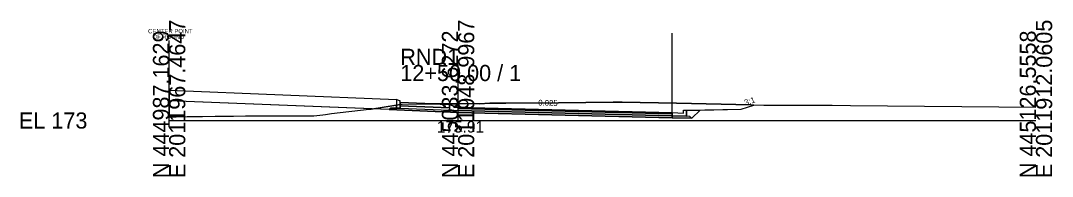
# Model space of a CAD drawing. Extents: x -26 to 153, y -10 to 6017.
# Drawn here: x -25.7 to 152.8, y 4990.3 to 5017.3 of the extents above; entities that cross this region are included whole.
import ezdxf

# ---------------------------------------------------------------- set-up
doc = ezdxf.new("R2010")
doc.units = 0
for name, color, linetype in [('Exist Cross Section Cell', 7, 'Continuous'), ('Exist XS Ground Line', 7, 'Continuous'), ('Prop CMT Conc Surface', 7, 'Continuous'), ('Prop CMT Concrete Structures', 7, 'Continuous'), ('Prop CMT Pvmt Course 1', 7, 'Continuous'), ('Prop CMT Pvmt Course 1 CG', 7, 'Continuous'), ('Prop CMT Pvmt Course 2', 7, 'Continuous'), ('Prop CMT Pvmt Course 3', 7, 'Continuous'), ('Prop CMT Pvmt Surface', 7, 'Continuous'), ('Prop CMT Shear Line', 7, 'Continuous'), ('Prop CMT Shear Line Text', 7, 'Continuous'), ('Prop CMT Slope Grass', 7, 'Continuous'), ('Prop CMT Subgrade Earthwork', 7, 'Continuous'), ('Prop XS Earthwork Shape', 7, 'Continuous'), ('Prop XS SE Text', 7, 'Continuous'), ('Prop XS Side Slope Text', 7, 'Continuous'), ('Scratch_Level_1', 7, 'Continuous')]:
    doc.layers.add(name, color=color, linetype=linetype)

msp = doc.modelspace()

# ---------------------------------------------------------------- linework, layer by layer
at = {"layer": 'Exist Cross Section Cell'}
for p, q in [((50, 5000), (50, 5009.64)), ((0, 5000), (50, 5000)), ((50, 5000), (150, 5000))]:
    msp.add_line(p, q, dxfattribs=at)
at = {"layer": 'Exist XS Ground Line'}
msp.add_lwpolyline([(0, 5000.62), (0.45, 5000.62), (1.21, 5000.65), (3.1, 5000.71), (4.34, 5000.71), (5.78, 5000.7), (7.98, 5000.75), (8.46, 5000.76), (8.92, 5000.77), (9.3, 5000.77), (11.15, 5000.77), (13.23, 5000.79), (14.09, 5000.8), (14.73, 5000.8), (16.55, 5000.82), (17.74, 5000.82), (19.21, 5000.82), (20.44, 5000.83), (21.66, 5000.84), (23.37, 5000.84), (24.41, 5000.84), (25.04, 5000.82), (25.54, 5000.87), (26.58, 5001), (27.09, 5001.06), (28.12, 5001.2), (34.63, 5001.94), (34.98, 5001.99), (40.35, 5002.86), (50, 5002.91), (52.83, 5002.93), (53.71, 5002.92), (55.52, 5002.98), (58.29, 5002.98), (67.4, 5003.08), (76.85, 5003.21), (77.24, 5003.21), (78.41, 5003.2), (87.81, 5003.01), (100.67, 5002.69), (102.93, 5002.64), (105.36, 5002.65), (108.91, 5002.66), (110.4, 5002.67), (111.72, 5002.68), (112.15, 5002.68), (114.72, 5002.66), (117.91, 5002.61), (150, 5002.32)], dxfattribs=at)
at = {"layer": 'Prop CMT Conc Surface'}
for points in [[(40, 5003.29), (39.96, 5003.39), (39.85, 5003.43), (39.34, 5003.62)], [(40, 5003.12), (40, 5003.29)], [(50, 5002.32), (49.25, 5002.34), (49.25, 5002.51), (48.5, 5002.76)], [(87.04, 5001.4), (89.03, 5001.27)], [(89.03, 5001.27), (89.03, 5001.77), (89.53, 5001.77)]]:
    msp.add_lwpolyline(points, dxfattribs=at)
at = {"layer": 'Prop CMT Concrete Structures'}
for points in [[(40, 5003.29), (39.96, 5003.39), (39.85, 5003.43), (39.34, 5003.62)], [(39.34, 5003.62), (39.34, 5002.12)], [(40, 5003.12), (40, 5003.29)], [(40, 5002.12), (40, 5003.12)], [(40, 5003.12), (40, 5002.54)], [(48.5, 5002.76), (40, 5003.1)], [(40, 5002.52), (48.5, 5002.18)], [(50, 5002.32), (49.25, 5002.34), (49.25, 5002.51), (48.5, 5002.76)], [(48.5, 5002.76), (48.5, 5001.78)], [(48.5, 5002.18), (48.5, 5002.76)], [(39.34, 5002.12), (40, 5002.12)], [(48.5, 5001.78), (50, 5001.74)], [(50, 5001.74), (50, 5002.32)], [(87.04, 5001.4), (89.03, 5001.27), (89.03, 5001.77), (89.53, 5001.77)], [(89.53, 5001.77), (89.53, 5000.75), (87.04, 5000.81)], [(87.04, 5000.81), (87.04, 5001.4)]]:
    msp.add_lwpolyline(points, dxfattribs=at)
at = {"layer": 'Prop CMT Pvmt Course 1'}
for points in [[(50, 5002.32), (87.04, 5001.4)], [(50, 5002.07), (50, 5002.32)], [(87.04, 5001.15), (50, 5002.07)], [(87.04, 5001.4), (87.04, 5001.15)]]:
    msp.add_lwpolyline(points, dxfattribs=at)
msp.add_lwpolyline([(50, 5002.07), (50, 5002.2), (50, 5002.2), (50, 5002.07)], close=True, dxfattribs=at)
at = {"layer": 'Prop CMT Pvmt Course 1 CG'}
for points in [[(50, 5001.41), (50, 5001.74)], [(87.04, 5000.81), (90.03, 5000.74), (90.37, 5000.4)], [(87.04, 5000.48), (87.04, 5000.81)], [(90.45, 5000.39), (87.04, 5000.48)]]:
    msp.add_lwpolyline(points, dxfattribs=at)
at = {"layer": 'Prop CMT Pvmt Course 2'}
for points in [[(50, 5001.74), (50, 5002.07)], [(50, 5002.07), (87.04, 5001.15)], [(87.04, 5000.81), (50, 5001.74)], [(87.04, 5001.15), (87.04, 5000.81)]]:
    msp.add_lwpolyline(points, dxfattribs=at)
at = {"layer": 'Prop CMT Pvmt Course 3'}
for points in [[(40, 5002.12), (48.5, 5001.78)], [(50, 5001.74), (87.04, 5000.81)], [(50, 5001.41), (50, 5001.74)], [(87.04, 5000.48), (50, 5001.41)], [(87.04, 5000.81), (87.04, 5000.48)]]:
    msp.add_lwpolyline(points, dxfattribs=at)
at = {"layer": 'Prop CMT Pvmt Surface'}
msp.add_lwpolyline([(50, 5002.32), (87.04, 5001.4)], dxfattribs=at)
at = {"layer": 'Prop CMT Shear Line'}
msp.add_line((0, 4998.87), (0, 5013.87), dxfattribs=at)
at = {"layer": 'Prop CMT Slope Grass'}
for p, q in [((39.34, 5003.6), (0, 5005.18)), ((38.06, 5001.89), (0, 5003.41))]:
    msp.add_line(p, q, dxfattribs=at)
msp.add_lwpolyline([(89.53, 5001.77), (99, 5001.96), (101.16, 5002.68)], dxfattribs=at)
at = {"layer": 'Prop CMT Subgrade Earthwork'}
for p, q in [((0, 5005.18), (0, 5000.62)), ((38.34, 5002.16), (38.06, 5001.89))]:
    msp.add_line(p, q, dxfattribs=at)
for points in [[(38.06, 5001.89), (50, 5001.41)], [(38.34, 5002.16), (39.34, 5002.12)], [(50, 5001.41), (87.04, 5000.48)], [(87.04, 5000.48), (90.45, 5000.39), (91.87, 5001.81)]]:
    msp.add_lwpolyline(points, dxfattribs=at)
at = {"layer": 'Prop XS Earthwork Shape'}
for points in [[(0, 5000.62), (0.45, 5000.62), (1.21, 5000.65), (3.1, 5000.71), (4.34, 5000.71), (5.78, 5000.7), (7.98, 5000.75), (8.46, 5000.76), (8.92, 5000.77), (9.3, 5000.77), (11.15, 5000.77), (13.23, 5000.79), (14.09, 5000.8), (14.73, 5000.8), (16.55, 5000.82), (17.74, 5000.82), (19.21, 5000.82), (20.44, 5000.83), (21.66, 5000.84), (23.37, 5000.84), (24.41, 5000.84), (25.04, 5000.82), (25.54, 5000.87), (26.58, 5001), (27.09, 5001.06), (28.12, 5001.2), (34.63, 5001.94), (34.98, 5001.99), (35.1, 5002.01), (0, 5003.41)], [(38.06, 5001.89), (35.1, 5002.01), (39.34, 5002.7), (39.34, 5002.12), (38.34, 5002.16)], [(89.53, 5001.77), (91.87, 5001.81), (90.45, 5000.39), (87.04, 5000.48), (50, 5001.41), (38.06, 5001.89), (38.34, 5002.16), (39.34, 5002.12), (40, 5002.12), (40, 5002.52), (48.5, 5002.18), (48.5, 5001.78), (50, 5001.74), (50, 5002.32), (87.04, 5001.4), (87.04, 5000.81), (89.53, 5000.75)], [(39.34, 5002.7), (40, 5002.81), (40, 5002.54), (40, 5002.52), (40, 5002.12), (39.34, 5002.12)], [(40, 5002.52), (40, 5002.54), (40, 5002.81), (40.35, 5002.86), (45.29, 5002.89), (48.5, 5002.76), (48.5, 5002.18)], [(89.53, 5001.77), (91.87, 5001.81), (99, 5001.96), (101.16, 5002.68), (100.67, 5002.69), (87.81, 5003.01), (78.41, 5003.2), (77.24, 5003.21), (76.85, 5003.21), (67.4, 5003.08), (58.29, 5002.98), (55.52, 5002.98), (53.71, 5002.92), (52.83, 5002.93), (50, 5002.91), (45.29, 5002.89), (48.5, 5002.76), (49.25, 5002.51), (49.25, 5002.34), (50, 5002.32), (87.04, 5001.4), (89.03, 5001.27), (89.03, 5001.77)], [(50, 5001.74), (50, 5002.32), (49.25, 5002.34), (49.25, 5002.51), (48.5, 5002.76), (48.5, 5002.18), (48.5, 5001.78)], [(89.03, 5001.77), (89.53, 5001.77), (89.53, 5000.75), (87.04, 5000.81), (87.04, 5001.4), (89.03, 5001.27)]]:
    msp.add_lwpolyline(points, close=True, dxfattribs=at)
at = {"layer": 'Scratch_Level_1'}
msp.add_line((87.04, 5000.92), (87.04, 5015.13), dxfattribs=at)

# ---------------------------------------------------------------- texts
at = {"layer": 'Exist Cross Section Cell'}
for s, p in [('E 2011967.4647', (2.8, 4990)), ('E 2011948.9967', (52.8, 4990)), ('E 2011912.0605', (152.8, 4990)), ('N 444987.1629', (0, 4990)), ('N 445033.6272', (50, 4990)), ('N 445126.5558', (150, 4990))]:
    msp.add_text(s, height=2.8, rotation=90, dxfattribs=at).set_placement(p)
for s, p in [('RND1', (40, 5009.64)), ('12+50.00 / 1', (40, 5006.84)), ('EL 173', (-26, 4998.6))]:
    msp.add_text(s, height=2.8, dxfattribs=at).set_placement(p)
at = {"layer": 'Exist XS Ground Line'}
msp.add_text('175.91', height=2, dxfattribs=at).set_placement((46.32, 4997.91))
at = {"layer": 'Prop CMT Shear Line Text'}
for s, p in [('CENTER POINT', (-3.64, 5015.12)), ('OF ROUND', (-2.88, 5014.14))]:
    msp.add_text(s, height=0.75, dxfattribs=at).set_placement(p)
at = {"layer": 'Prop XS SE Text'}
msp.add_text('0.025', height=1, rotation=358.5613, dxfattribs=at).set_placement((63.87, 5002.6))
at = {"layer": 'Prop XS Side Slope Text'}
msp.add_text('3:1', height=1, rotation=18.4349, dxfattribs=at).set_placement((99.73, 5002.6))

doc.saveas('drawing.dxf')
